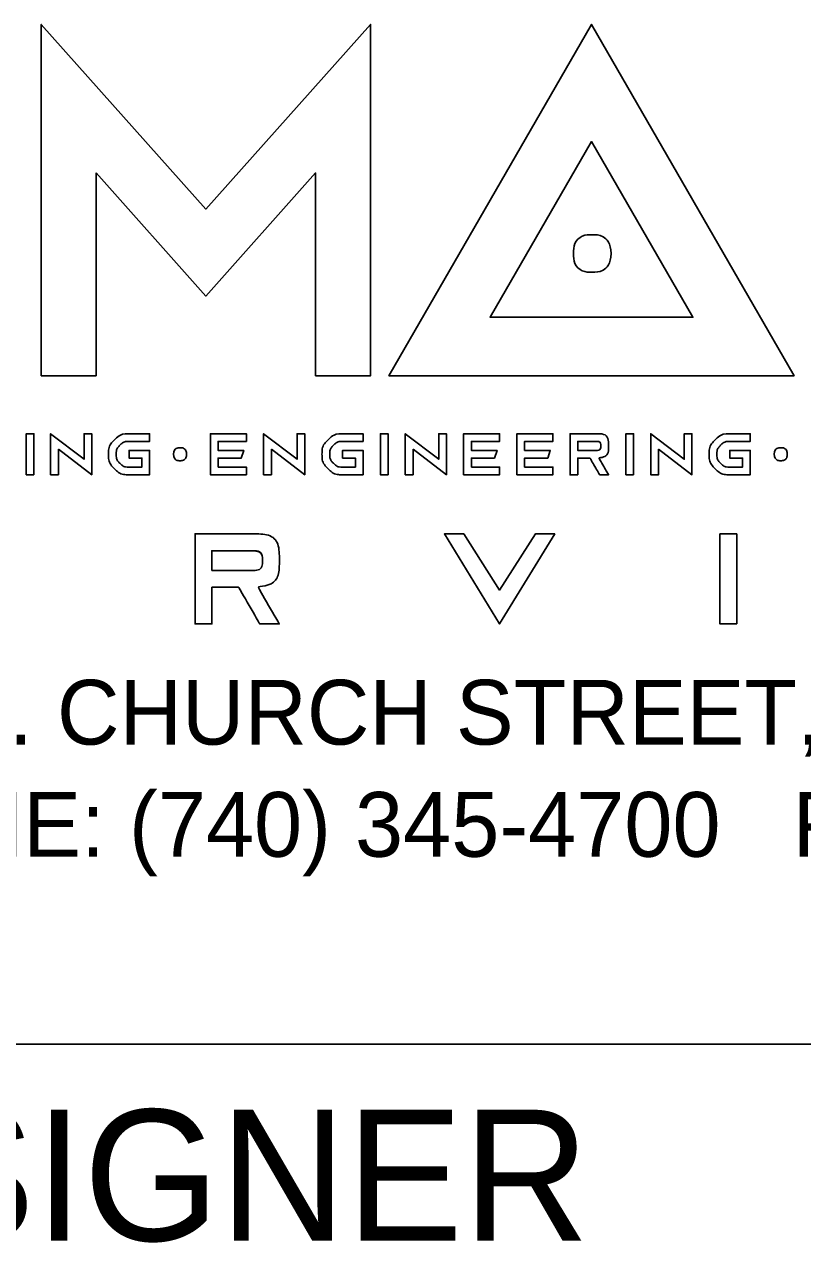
# Model space of a CAD drawing. Extents: x 0 to 34, y 0 to 22.
# Drawn here: x 32.317 to 32.911, y 2.849 to 3.778 of the extents above; entities that cross this region are included whole.
import ezdxf

# ---------------------------------------------------------------- set-up
doc = ezdxf.new("R2010")
doc.units = 0
for name, color, linetype in [('BORDER', 7, 'Continuous'), ('SH_Border', 7, 'Continuous'), ('SH_Data', 7, 'Continuous')]:
    doc.layers.add(name, color=color, linetype=linetype)

msp = doc.modelspace()

# ---------------------------------------------------------------- linework, layer by layer
at = {"layer": 'BORDER'}
for p, q in [((32.32986, 3.51002), (32.32986, 3.77816)), ((32.32986, 3.77816), (32.45556, 3.6372)), ((32.45556, 3.6372), (32.58125, 3.77816)), ((32.58125, 3.77816), (32.58125, 3.51002)), ((32.37176, 3.66476), (32.37176, 3.51002)), ((32.45556, 3.57079), (32.37176, 3.66476)), ((32.53935, 3.66476), (32.45556, 3.57079)), ((32.53935, 3.51002), (32.53935, 3.66476)), ((32.37176, 3.51002), (32.32986, 3.51002)), ((32.58125, 3.51002), (32.53935, 3.51002)), ((32.3184, 3.43446), (32.3184, 3.46585)), ((32.3184, 3.46585), (32.32429, 3.46585)), ((32.32429, 3.46585), (32.32429, 3.43446)), ((32.33705, 3.43446), (32.33705, 3.46585)), ((32.33705, 3.46585), (32.36255, 3.44639)), ((32.36255, 3.44639), (32.36255, 3.46585)), ((32.36255, 3.46585), (32.36844, 3.46585)), ((32.36844, 3.46585), (32.36844, 3.43446)), ((32.45904, 3.43446), (32.45904, 3.46585)), ((32.45904, 3.46585), (32.4865, 3.46585)), ((32.4865, 3.45997), (32.46493, 3.45997)), ((32.46493, 3.45997), (32.46493, 3.4531)), ((32.4865, 3.46585), (32.4865, 3.45997)), ((32.49967, 3.43446), (32.49967, 3.46585)), ((32.49967, 3.46585), (32.52517, 3.44639)), ((32.52517, 3.44639), (32.52517, 3.46585)), ((32.52517, 3.46585), (32.53105, 3.46585)), ((32.53105, 3.46585), (32.53105, 3.43446)), ((32.58877, 3.43446), (32.58877, 3.46585)), ((32.58877, 3.46585), (32.59465, 3.46585)), ((32.59465, 3.46585), (32.59465, 3.43446)), ((32.60782, 3.43446), (32.60782, 3.46585)), ((32.60782, 3.46585), (32.63332, 3.44639)), ((32.63332, 3.44639), (32.63332, 3.46585)), ((32.63332, 3.46585), (32.6392, 3.46585)), ((32.6392, 3.46585), (32.6392, 3.43446)), ((32.65237, 3.43446), (32.65237, 3.46585)), ((32.65237, 3.46585), (32.67983, 3.46585)), ((32.67983, 3.45997), (32.65825, 3.45997)), ((32.65825, 3.45997), (32.65825, 3.4531)), ((32.67983, 3.46585), (32.67983, 3.45997)), ((32.69299, 3.43446), (32.69299, 3.46585)), ((32.69299, 3.46585), (32.72046, 3.46585)), ((32.72046, 3.45997), (32.69888, 3.45997)), ((32.69888, 3.45997), (32.69888, 3.4531)), ((32.72046, 3.46585), (32.72046, 3.45997)), ((32.77621, 3.43446), (32.77621, 3.46585)), ((32.77621, 3.46585), (32.78209, 3.46585)), ((32.78209, 3.46585), (32.78209, 3.43446)), ((32.79526, 3.43446), (32.79526, 3.46585)), ((32.79526, 3.46585), (32.82076, 3.44639)), ((32.82076, 3.44639), (32.82076, 3.46585)), ((32.82076, 3.46585), (32.82664, 3.46585)), ((32.82664, 3.46585), (32.82664, 3.43446)), ((32.34294, 3.45393), (32.34294, 3.43446)), ((32.36844, 3.43446), (32.34294, 3.45393)), ((32.46493, 3.4531), (32.48454, 3.4531)), ((32.48454, 3.4531), (32.48258, 3.44722)), ((32.50555, 3.45393), (32.50555, 3.43446)), ((32.53105, 3.43446), (32.50555, 3.45393)), ((32.6137, 3.45393), (32.6137, 3.43446)), ((32.6392, 3.43446), (32.6137, 3.45393)), ((32.65825, 3.4531), (32.67787, 3.4531)), ((32.67787, 3.4531), (32.67591, 3.44722)), ((32.69888, 3.4531), (32.71849, 3.4531)), ((32.71849, 3.4531), (32.71653, 3.44722)), ((32.80114, 3.45393), (32.80114, 3.43446)), ((32.82664, 3.43446), (32.80114, 3.45393)), ((32.48258, 3.44722), (32.46493, 3.44722)), ((32.46493, 3.44722), (32.46493, 3.44035)), ((32.46493, 3.44035), (32.4865, 3.44035)), ((32.4865, 3.44035), (32.4865, 3.43446)), ((32.67591, 3.44722), (32.65825, 3.44722)), ((32.65825, 3.44722), (32.65825, 3.44035)), ((32.65825, 3.44035), (32.67983, 3.44035)), ((32.67983, 3.44035), (32.67983, 3.43446)), ((32.71653, 3.44722), (32.69888, 3.44722)), ((32.69888, 3.44722), (32.69888, 3.44035)), ((32.69888, 3.44035), (32.72046, 3.44035)), ((32.72046, 3.44035), (32.72046, 3.43446)), ((32.32429, 3.43446), (32.3184, 3.43446)), ((32.34294, 3.43446), (32.33705, 3.43446)), ((32.4865, 3.43446), (32.45904, 3.43446)), ((32.50555, 3.43446), (32.49967, 3.43446)), ((32.59465, 3.43446), (32.58877, 3.43446)), ((32.6137, 3.43446), (32.60782, 3.43446)), ((32.67983, 3.43446), (32.65237, 3.43446)), ((32.72046, 3.43446), (32.69299, 3.43446)), ((32.78209, 3.43446), (32.77621, 3.43446)), ((32.80114, 3.43446), (32.79526, 3.43446)), ((32.67985, 3.32072), (32.63773, 3.38941)), ((32.63773, 3.38941), (32.65258, 3.38941)), ((32.65258, 3.38941), (32.67985, 3.34648)), ((32.67985, 3.34648), (32.70711, 3.38941)), ((32.72196, 3.38941), (32.67985, 3.32072)), ((32.70711, 3.38941), (32.72196, 3.38941)), ((32.84802, 3.32072), (32.84802, 3.38941)), ((32.84802, 3.38941), (32.8609, 3.38941)), ((32.8609, 3.38941), (32.8609, 3.32072)), ((32.8609, 3.32072), (32.84802, 3.32072))]:
    msp.add_line(p, q, dxfattribs=at)
for points in [[(32.37176, 3.66476), (32.37176, 3.51002), (32.32986, 3.51002), (32.32986, 3.77816), (32.45556, 3.6372), (32.58125, 3.77816), (32.58125, 3.51002), (32.53935, 3.51002), (32.53935, 3.66476), (32.45556, 3.57079), (32.37176, 3.66476)], [(32.59529, 3.51002), (32.74998, 3.77816), (32.90467, 3.51002), (32.59529, 3.51002)], [(32.67256, 3.55468), (32.8274, 3.55468), (32.74998, 3.68868), (32.67256, 3.55468)], [(32.32429, 3.43446), (32.3184, 3.43446), (32.3184, 3.46585), (32.32429, 3.46585), (32.32429, 3.43446)], [(32.34294, 3.45393), (32.34294, 3.43446), (32.33705, 3.43446), (32.33705, 3.46585), (32.36255, 3.44639), (32.36255, 3.46585), (32.36844, 3.46585), (32.36844, 3.43446), (32.34294, 3.45393)], [(32.46493, 3.44035), (32.4865, 3.44035), (32.4865, 3.43446), (32.45904, 3.43446), (32.45904, 3.46585), (32.4865, 3.46585), (32.4865, 3.45997), (32.46493, 3.45997), (32.46493, 3.4531), (32.48454, 3.4531), (32.48258, 3.44722), (32.46493, 3.44722), (32.46493, 3.44035)], [(32.50555, 3.45393), (32.50555, 3.43446), (32.49967, 3.43446), (32.49967, 3.46585), (32.52517, 3.44639), (32.52517, 3.46585), (32.53105, 3.46585), (32.53105, 3.43446), (32.50555, 3.45393)], [(32.59465, 3.43446), (32.58877, 3.43446), (32.58877, 3.46585), (32.59465, 3.46585), (32.59465, 3.43446)], [(32.6137, 3.45393), (32.6137, 3.43446), (32.60782, 3.43446), (32.60782, 3.46585), (32.63332, 3.44639), (32.63332, 3.46585), (32.6392, 3.46585), (32.6392, 3.43446), (32.6137, 3.45393)], [(32.65825, 3.44035), (32.67983, 3.44035), (32.67983, 3.43446), (32.65237, 3.43446), (32.65237, 3.46585), (32.67983, 3.46585), (32.67983, 3.45997), (32.65825, 3.45997), (32.65825, 3.4531), (32.67787, 3.4531), (32.67591, 3.44722), (32.65825, 3.44722), (32.65825, 3.44035)], [(32.69888, 3.44035), (32.72046, 3.44035), (32.72046, 3.43446), (32.69299, 3.43446), (32.69299, 3.46585), (32.72046, 3.46585), (32.72046, 3.45997), (32.69888, 3.45997), (32.69888, 3.4531), (32.71849, 3.4531), (32.71653, 3.44722), (32.69888, 3.44722), (32.69888, 3.44035)], [(32.78209, 3.43446), (32.77621, 3.43446), (32.77621, 3.46585), (32.78209, 3.46585), (32.78209, 3.43446)], [(32.80114, 3.45393), (32.80114, 3.43446), (32.79526, 3.43446), (32.79526, 3.46585), (32.82076, 3.44639), (32.82076, 3.46585), (32.82664, 3.46585), (32.82664, 3.43446), (32.80114, 3.45393)], [(32.65258, 3.38941), (32.67985, 3.34648), (32.70711, 3.38941), (32.72196, 3.38941), (32.67985, 3.32072), (32.63773, 3.38941), (32.65258, 3.38941)], [(32.8609, 3.32072), (32.84802, 3.32072), (32.84802, 3.38941), (32.8609, 3.38941), (32.8609, 3.32072)]]:
    msp.add_lwpolyline(points, dxfattribs=at)
for points in [[(32.90467, 3.51002), (32.74998, 3.77816), (32.59529, 3.51002)], [(32.74998, 3.68868), (32.8274, 3.55468), (32.67256, 3.55468)]]:
    msp.add_lwpolyline(points, close=True, dxfattribs=at)
for points, degree in [([(32.76488, 3.60333), (32.76488, 3.59543), (32.75847, 3.58902), (32.75057, 3.58902), (32.74267, 3.58902), (32.73626, 3.59543), (32.73626, 3.60333), (32.73626, 3.61124), (32.74267, 3.61764), (32.75057, 3.61764), (32.75847, 3.61764), (32.76488, 3.61124), (32.76488, 3.60333)], 3), ([(32.76488, 3.60333), (32.76488, 3.59543), (32.75847, 3.58902), (32.75057, 3.58902), (32.74267, 3.58902), (32.73626, 3.59543), (32.73626, 3.60333), (32.73626, 3.61124), (32.74267, 3.61764), (32.75057, 3.61764), (32.75847, 3.61764), (32.76488, 3.61124), (32.76488, 3.60333)], 3), ([(32.39689, 3.46585), (32.39689, 3.46585), (32.41259, 3.46585), (32.41259, 3.46585), (32.41259, 3.46585), (32.41259, 3.45997), (32.41259, 3.45997), (32.41259, 3.45997), (32.39689, 3.45997), (32.39689, 3.45997), (32.39419, 3.45997), (32.39187, 3.45901), (32.38996, 3.45709), (32.38804, 3.45518), (32.38709, 3.45287), (32.38709, 3.45016), (32.38709, 3.44745), (32.38804, 3.44514), (32.38996, 3.44322), (32.39187, 3.44131), (32.39419, 3.44035), (32.39689, 3.44035), (32.39689, 3.44035), (32.4067, 3.44035), (32.4067, 3.44035), (32.4067, 3.44035), (32.4067, 3.44722), (32.4067, 3.44722), (32.4067, 3.44722), (32.39689, 3.44722), (32.39689, 3.44722), (32.39689, 3.44722), (32.39689, 3.4531), (32.39689, 3.4531), (32.39689, 3.4531), (32.41259, 3.4531), (32.41259, 3.4531), (32.41259, 3.4531), (32.41259, 3.43446), (32.41259, 3.43446), (32.41259, 3.43446), (32.39689, 3.43446), (32.39689, 3.43446), (32.39256, 3.43446), (32.38887, 3.436), (32.3858, 3.43907), (32.38273, 3.44213), (32.3812, 3.44583), (32.3812, 3.45016), (32.3812, 3.45449), (32.38273, 3.45818), (32.3858, 3.46125), (32.38887, 3.46432), (32.39256, 3.46585), (32.39689, 3.46585)], 3), ([(32.39689, 3.46585), (32.39689, 3.46585), (32.41259, 3.46585), (32.41259, 3.46585), (32.41259, 3.46585), (32.41259, 3.45997), (32.41259, 3.45997), (32.41259, 3.45997), (32.39689, 3.45997), (32.39689, 3.45997), (32.39419, 3.45997), (32.39187, 3.45901), (32.38996, 3.45709), (32.38804, 3.45518), (32.38709, 3.45287), (32.38709, 3.45016), (32.38709, 3.44745), (32.38804, 3.44514), (32.38996, 3.44322), (32.39187, 3.44131), (32.39419, 3.44035), (32.39689, 3.44035), (32.39689, 3.44035), (32.4067, 3.44035), (32.4067, 3.44035), (32.4067, 3.44035), (32.4067, 3.44722), (32.4067, 3.44722), (32.4067, 3.44722), (32.39689, 3.44722), (32.39689, 3.44722), (32.39689, 3.44722), (32.39689, 3.4531), (32.39689, 3.4531), (32.39689, 3.4531), (32.41259, 3.4531), (32.41259, 3.4531), (32.41259, 3.4531), (32.41259, 3.43446), (32.41259, 3.43446), (32.41259, 3.43446), (32.39689, 3.43446), (32.39689, 3.43446), (32.39256, 3.43446), (32.38887, 3.436), (32.3858, 3.43907), (32.38273, 3.44213), (32.3812, 3.44583), (32.3812, 3.45016), (32.3812, 3.45449), (32.38273, 3.45818), (32.3858, 3.46125), (32.38887, 3.46432), (32.39256, 3.46585), (32.39689, 3.46585)], 3), ([(32.55991, 3.46585), (32.55991, 3.46585), (32.5756, 3.46585), (32.5756, 3.46585), (32.5756, 3.46585), (32.5756, 3.45997), (32.5756, 3.45997), (32.5756, 3.45997), (32.55991, 3.45997), (32.55991, 3.45997), (32.5572, 3.45997), (32.55489, 3.45901), (32.55298, 3.45709), (32.55106, 3.45518), (32.5501, 3.45286), (32.5501, 3.45016), (32.5501, 3.44745), (32.55106, 3.44514), (32.55298, 3.44322), (32.55489, 3.44131), (32.5572, 3.44035), (32.55991, 3.44035), (32.55991, 3.44035), (32.56972, 3.44035), (32.56972, 3.44035), (32.56972, 3.44035), (32.56972, 3.44722), (32.56972, 3.44722), (32.56972, 3.44722), (32.55991, 3.44722), (32.55991, 3.44722), (32.55991, 3.44722), (32.55991, 3.4531), (32.55991, 3.4531), (32.55991, 3.4531), (32.5756, 3.4531), (32.5756, 3.4531), (32.5756, 3.4531), (32.5756, 3.43446), (32.5756, 3.43446), (32.5756, 3.43446), (32.55991, 3.43446), (32.55991, 3.43446), (32.55558, 3.43446), (32.55188, 3.436), (32.54882, 3.43906), (32.54575, 3.44213), (32.54422, 3.44583), (32.54422, 3.45016), (32.54422, 3.45449), (32.54575, 3.45818), (32.54882, 3.46125), (32.55188, 3.46432), (32.55558, 3.46585), (32.55991, 3.46585)], 3), ([(32.55991, 3.46585), (32.55991, 3.46585), (32.5756, 3.46585), (32.5756, 3.46585), (32.5756, 3.46585), (32.5756, 3.45997), (32.5756, 3.45997), (32.5756, 3.45997), (32.55991, 3.45997), (32.55991, 3.45997), (32.5572, 3.45997), (32.55489, 3.45901), (32.55298, 3.45709), (32.55106, 3.45518), (32.5501, 3.45286), (32.5501, 3.45016), (32.5501, 3.44745), (32.55106, 3.44514), (32.55298, 3.44322), (32.55489, 3.44131), (32.5572, 3.44035), (32.55991, 3.44035), (32.55991, 3.44035), (32.56972, 3.44035), (32.56972, 3.44035), (32.56972, 3.44035), (32.56972, 3.44722), (32.56972, 3.44722), (32.56972, 3.44722), (32.55991, 3.44722), (32.55991, 3.44722), (32.55991, 3.44722), (32.55991, 3.4531), (32.55991, 3.4531), (32.55991, 3.4531), (32.5756, 3.4531), (32.5756, 3.4531), (32.5756, 3.4531), (32.5756, 3.43446), (32.5756, 3.43446), (32.5756, 3.43446), (32.55991, 3.43446), (32.55991, 3.43446), (32.55558, 3.43446), (32.55188, 3.436), (32.54882, 3.43906), (32.54575, 3.44213), (32.54422, 3.44583), (32.54422, 3.45016), (32.54422, 3.45449), (32.54575, 3.45818), (32.54882, 3.46125), (32.55188, 3.46432), (32.55558, 3.46585), (32.55991, 3.46585)], 3), ([(32.73362, 3.46585), (32.73362, 3.46585), (32.73362, 3.43446), (32.73362, 3.43446)], 2), ([(32.73362, 3.46585), (32.73362, 3.46585), (32.75324, 3.46585), (32.75324, 3.46585), (32.75977, 3.46585), (32.76304, 3.46274), (32.76304, 3.45653), (32.76304, 3.45111), (32.76055, 3.44805), (32.75555, 3.44737), (32.75555, 3.44737), (32.763, 3.43446), (32.763, 3.43446), (32.763, 3.43446), (32.7562, 3.43446), (32.7562, 3.43446), (32.7562, 3.43446), (32.74884, 3.44722), (32.74884, 3.44722), (32.74884, 3.44722), (32.7395, 3.44722), (32.7395, 3.44722), (32.7395, 3.44722), (32.7395, 3.43446), (32.7395, 3.43446), (32.7395, 3.43446), (32.73362, 3.43446), (32.73362, 3.43446), (32.73362, 3.43446), (32.73362, 3.46585), (32.73362, 3.46585)], 3), ([(32.73362, 3.43446), (32.73362, 3.43446), (32.7395, 3.43446), (32.7395, 3.43446), (32.7395, 3.43446), (32.7395, 3.44722), (32.7395, 3.44722), (32.7395, 3.44722), (32.74884, 3.44722), (32.74884, 3.44722), (32.74884, 3.44722), (32.7562, 3.43446), (32.7562, 3.43446), (32.7562, 3.43446), (32.763, 3.43446), (32.763, 3.43446), (32.763, 3.43446), (32.75555, 3.44737), (32.75555, 3.44737), (32.76055, 3.44805), (32.76304, 3.45111), (32.76304, 3.45653), (32.76304, 3.46274), (32.75977, 3.46585), (32.75324, 3.46585), (32.75324, 3.46585), (32.73362, 3.46585), (32.73362, 3.46585)], 3), ([(32.7395, 3.45997), (32.7395, 3.45997), (32.75324, 3.45997), (32.75324, 3.45997)], 2), ([(32.7395, 3.45997), (32.7395, 3.45997), (32.7395, 3.4531), (32.7395, 3.4531), (32.7395, 3.4531), (32.75324, 3.4531), (32.75324, 3.4531), (32.75585, 3.4531), (32.75716, 3.45424), (32.75716, 3.45653), (32.75716, 3.45882), (32.75585, 3.45997), (32.75324, 3.45997), (32.75324, 3.45997), (32.7395, 3.45997), (32.7395, 3.45997)], 3), ([(32.75324, 3.45997), (32.75585, 3.45997), (32.75716, 3.45882), (32.75716, 3.45653), (32.75716, 3.45424), (32.75585, 3.4531), (32.75324, 3.4531), (32.75324, 3.4531), (32.7395, 3.4531), (32.7395, 3.4531), (32.7395, 3.4531), (32.7395, 3.45997), (32.7395, 3.45997)], 3), ([(32.8555, 3.46585), (32.8555, 3.46585), (32.87119, 3.46585), (32.87119, 3.46585), (32.87119, 3.46585), (32.87119, 3.45997), (32.87119, 3.45997), (32.87119, 3.45997), (32.8555, 3.45997), (32.8555, 3.45997), (32.85279, 3.45997), (32.85048, 3.45901), (32.84857, 3.45709), (32.84665, 3.45518), (32.84569, 3.45286), (32.84569, 3.45016), (32.84569, 3.44745), (32.84665, 3.44514), (32.84857, 3.44322), (32.85048, 3.44131), (32.85279, 3.44035), (32.8555, 3.44035), (32.8555, 3.44035), (32.86531, 3.44035), (32.86531, 3.44035), (32.86531, 3.44035), (32.86531, 3.44722), (32.86531, 3.44722), (32.86531, 3.44722), (32.8555, 3.44722), (32.8555, 3.44722), (32.8555, 3.44722), (32.8555, 3.4531), (32.8555, 3.4531), (32.8555, 3.4531), (32.87119, 3.4531), (32.87119, 3.4531), (32.87119, 3.4531), (32.87119, 3.43446), (32.87119, 3.43446), (32.87119, 3.43446), (32.8555, 3.43446), (32.8555, 3.43446), (32.85117, 3.43446), (32.84747, 3.436), (32.84441, 3.43906), (32.84134, 3.44213), (32.83981, 3.44583), (32.83981, 3.45016), (32.83981, 3.45449), (32.84134, 3.45818), (32.84441, 3.46125), (32.84747, 3.46432), (32.85117, 3.46585), (32.8555, 3.46585)], 3), ([(32.8555, 3.46585), (32.8555, 3.46585), (32.87119, 3.46585), (32.87119, 3.46585), (32.87119, 3.46585), (32.87119, 3.45997), (32.87119, 3.45997), (32.87119, 3.45997), (32.8555, 3.45997), (32.8555, 3.45997), (32.85279, 3.45997), (32.85048, 3.45901), (32.84857, 3.45709), (32.84665, 3.45518), (32.84569, 3.45286), (32.84569, 3.45016), (32.84569, 3.44745), (32.84665, 3.44514), (32.84857, 3.44322), (32.85048, 3.44131), (32.85279, 3.44035), (32.8555, 3.44035), (32.8555, 3.44035), (32.86531, 3.44035), (32.86531, 3.44035), (32.86531, 3.44035), (32.86531, 3.44722), (32.86531, 3.44722), (32.86531, 3.44722), (32.8555, 3.44722), (32.8555, 3.44722), (32.8555, 3.44722), (32.8555, 3.4531), (32.8555, 3.4531), (32.8555, 3.4531), (32.87119, 3.4531), (32.87119, 3.4531), (32.87119, 3.4531), (32.87119, 3.43446), (32.87119, 3.43446), (32.87119, 3.43446), (32.8555, 3.43446), (32.8555, 3.43446), (32.85117, 3.43446), (32.84747, 3.436), (32.84441, 3.43906), (32.84134, 3.44213), (32.83981, 3.44583), (32.83981, 3.45016), (32.83981, 3.45449), (32.84134, 3.45818), (32.84441, 3.46125), (32.84747, 3.46432), (32.85117, 3.46585), (32.8555, 3.46585)], 3), ([(32.43088, 3.45013), (32.43083, 3.45292), (32.43309, 3.4551), (32.43581, 3.4551), (32.43854, 3.4551), (32.44075, 3.45292), (32.44075, 3.45018), (32.44075, 3.44739), (32.43859, 3.44522), (32.43581, 3.44522), (32.43309, 3.44522), (32.43088, 3.44735), (32.43088, 3.45013)], 3), ([(32.43088, 3.45013), (32.43083, 3.45292), (32.43309, 3.4551), (32.43581, 3.4551), (32.43854, 3.4551), (32.44075, 3.45292), (32.44075, 3.45018), (32.44075, 3.44739), (32.43859, 3.44522), (32.43581, 3.44522), (32.43309, 3.44522), (32.43088, 3.44735), (32.43088, 3.45013)], 3), ([(32.88948, 3.45013), (32.88943, 3.45292), (32.89169, 3.4551), (32.89442, 3.4551), (32.89715, 3.4551), (32.89936, 3.45292), (32.89936, 3.45018), (32.89936, 3.44739), (32.89719, 3.44522), (32.89442, 3.44522), (32.89169, 3.44522), (32.88948, 3.44735), (32.88948, 3.45013)], 3), ([(32.88948, 3.45013), (32.88943, 3.45292), (32.89169, 3.4551), (32.89442, 3.4551), (32.89715, 3.4551), (32.89936, 3.45292), (32.89936, 3.45018), (32.89936, 3.44739), (32.89719, 3.44522), (32.89442, 3.44522), (32.89169, 3.44522), (32.88948, 3.44735), (32.88948, 3.45013)], 3), ([(32.44727, 3.38941), (32.44727, 3.38941), (32.44727, 3.32072), (32.44727, 3.32072)], 2), ([(32.44727, 3.32072), (32.44727, 3.32072), (32.46015, 3.32072), (32.46015, 3.32072), (32.46015, 3.32072), (32.46015, 3.34863), (32.46015, 3.34863), (32.46015, 3.34863), (32.48058, 3.34863), (32.48058, 3.34863), (32.48058, 3.34863), (32.49668, 3.32072), (32.49668, 3.32072), (32.49668, 3.32072), (32.51158, 3.32072), (32.51158, 3.32072), (32.51158, 3.32072), (32.49527, 3.34897), (32.49527, 3.34897), (32.5062, 3.35046), (32.51167, 3.35714), (32.51167, 3.36902), (32.51167, 3.38261), (32.50451, 3.38941), (32.4902, 3.38941), (32.4902, 3.38941), (32.44727, 3.38941), (32.44727, 3.38941)], 3), ([(32.44727, 3.38941), (32.44727, 3.38941), (32.4902, 3.38941), (32.4902, 3.38941), (32.50451, 3.38941), (32.51167, 3.38261), (32.51167, 3.36902), (32.51167, 3.35714), (32.5062, 3.35046), (32.49527, 3.34897), (32.49527, 3.34897), (32.51158, 3.32072), (32.51158, 3.32072), (32.51158, 3.32072), (32.49668, 3.32072), (32.49668, 3.32072), (32.49668, 3.32072), (32.48058, 3.34863), (32.48058, 3.34863), (32.48058, 3.34863), (32.46015, 3.34863), (32.46015, 3.34863), (32.46015, 3.34863), (32.46015, 3.32072), (32.46015, 3.32072), (32.46015, 3.32072), (32.44727, 3.32072), (32.44727, 3.32072), (32.44727, 3.32072), (32.44727, 3.38941), (32.44727, 3.38941)], 3), ([(32.46015, 3.37653), (32.46015, 3.37653), (32.4902, 3.37653), (32.4902, 3.37653)], 2), ([(32.4902, 3.37653), (32.49593, 3.37653), (32.49879, 3.37403), (32.49879, 3.36902), (32.49879, 3.36401), (32.49593, 3.36151), (32.4902, 3.36151), (32.4902, 3.36151), (32.46015, 3.36151), (32.46015, 3.36151), (32.46015, 3.36151), (32.46015, 3.37653), (32.46015, 3.37653)], 3), ([(32.46015, 3.37653), (32.46015, 3.37653), (32.46015, 3.36151), (32.46015, 3.36151), (32.46015, 3.36151), (32.4902, 3.36151), (32.4902, 3.36151), (32.49593, 3.36151), (32.49879, 3.36401), (32.49879, 3.36902), (32.49879, 3.37403), (32.49593, 3.37653), (32.4902, 3.37653), (32.4902, 3.37653), (32.46015, 3.37653), (32.46015, 3.37653)], 3)]:
    msp.add_open_spline(points, degree=degree, dxfattribs=at)
at = {"layer": 'SH_Border'}
msp.add_line((32, 3), (33.5, 3), dxfattribs=at)

# ---------------------------------------------------------------- texts
at = {"layer": 'BORDER'}
for s, p in [('88 W. CHURCH STREET, NEWARK, OHIO 43055', (32.15108, 3.22861)), ('PHONE: (740) 345-4700   FAX: (740) 522-4706', (32.12535, 3.14302))]:
    msp.add_text(s, height=0.0493871, dxfattribs=at).set_placement(p)
at = {"layer": 'SH_Data'}
msp.add_text('DESIGNER', height=0.1, dxfattribs=at).set_placement((32.05, 2.85))

doc.saveas('drawing.dxf')
